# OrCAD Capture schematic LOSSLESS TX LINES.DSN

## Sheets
1 PAGE3: size A0
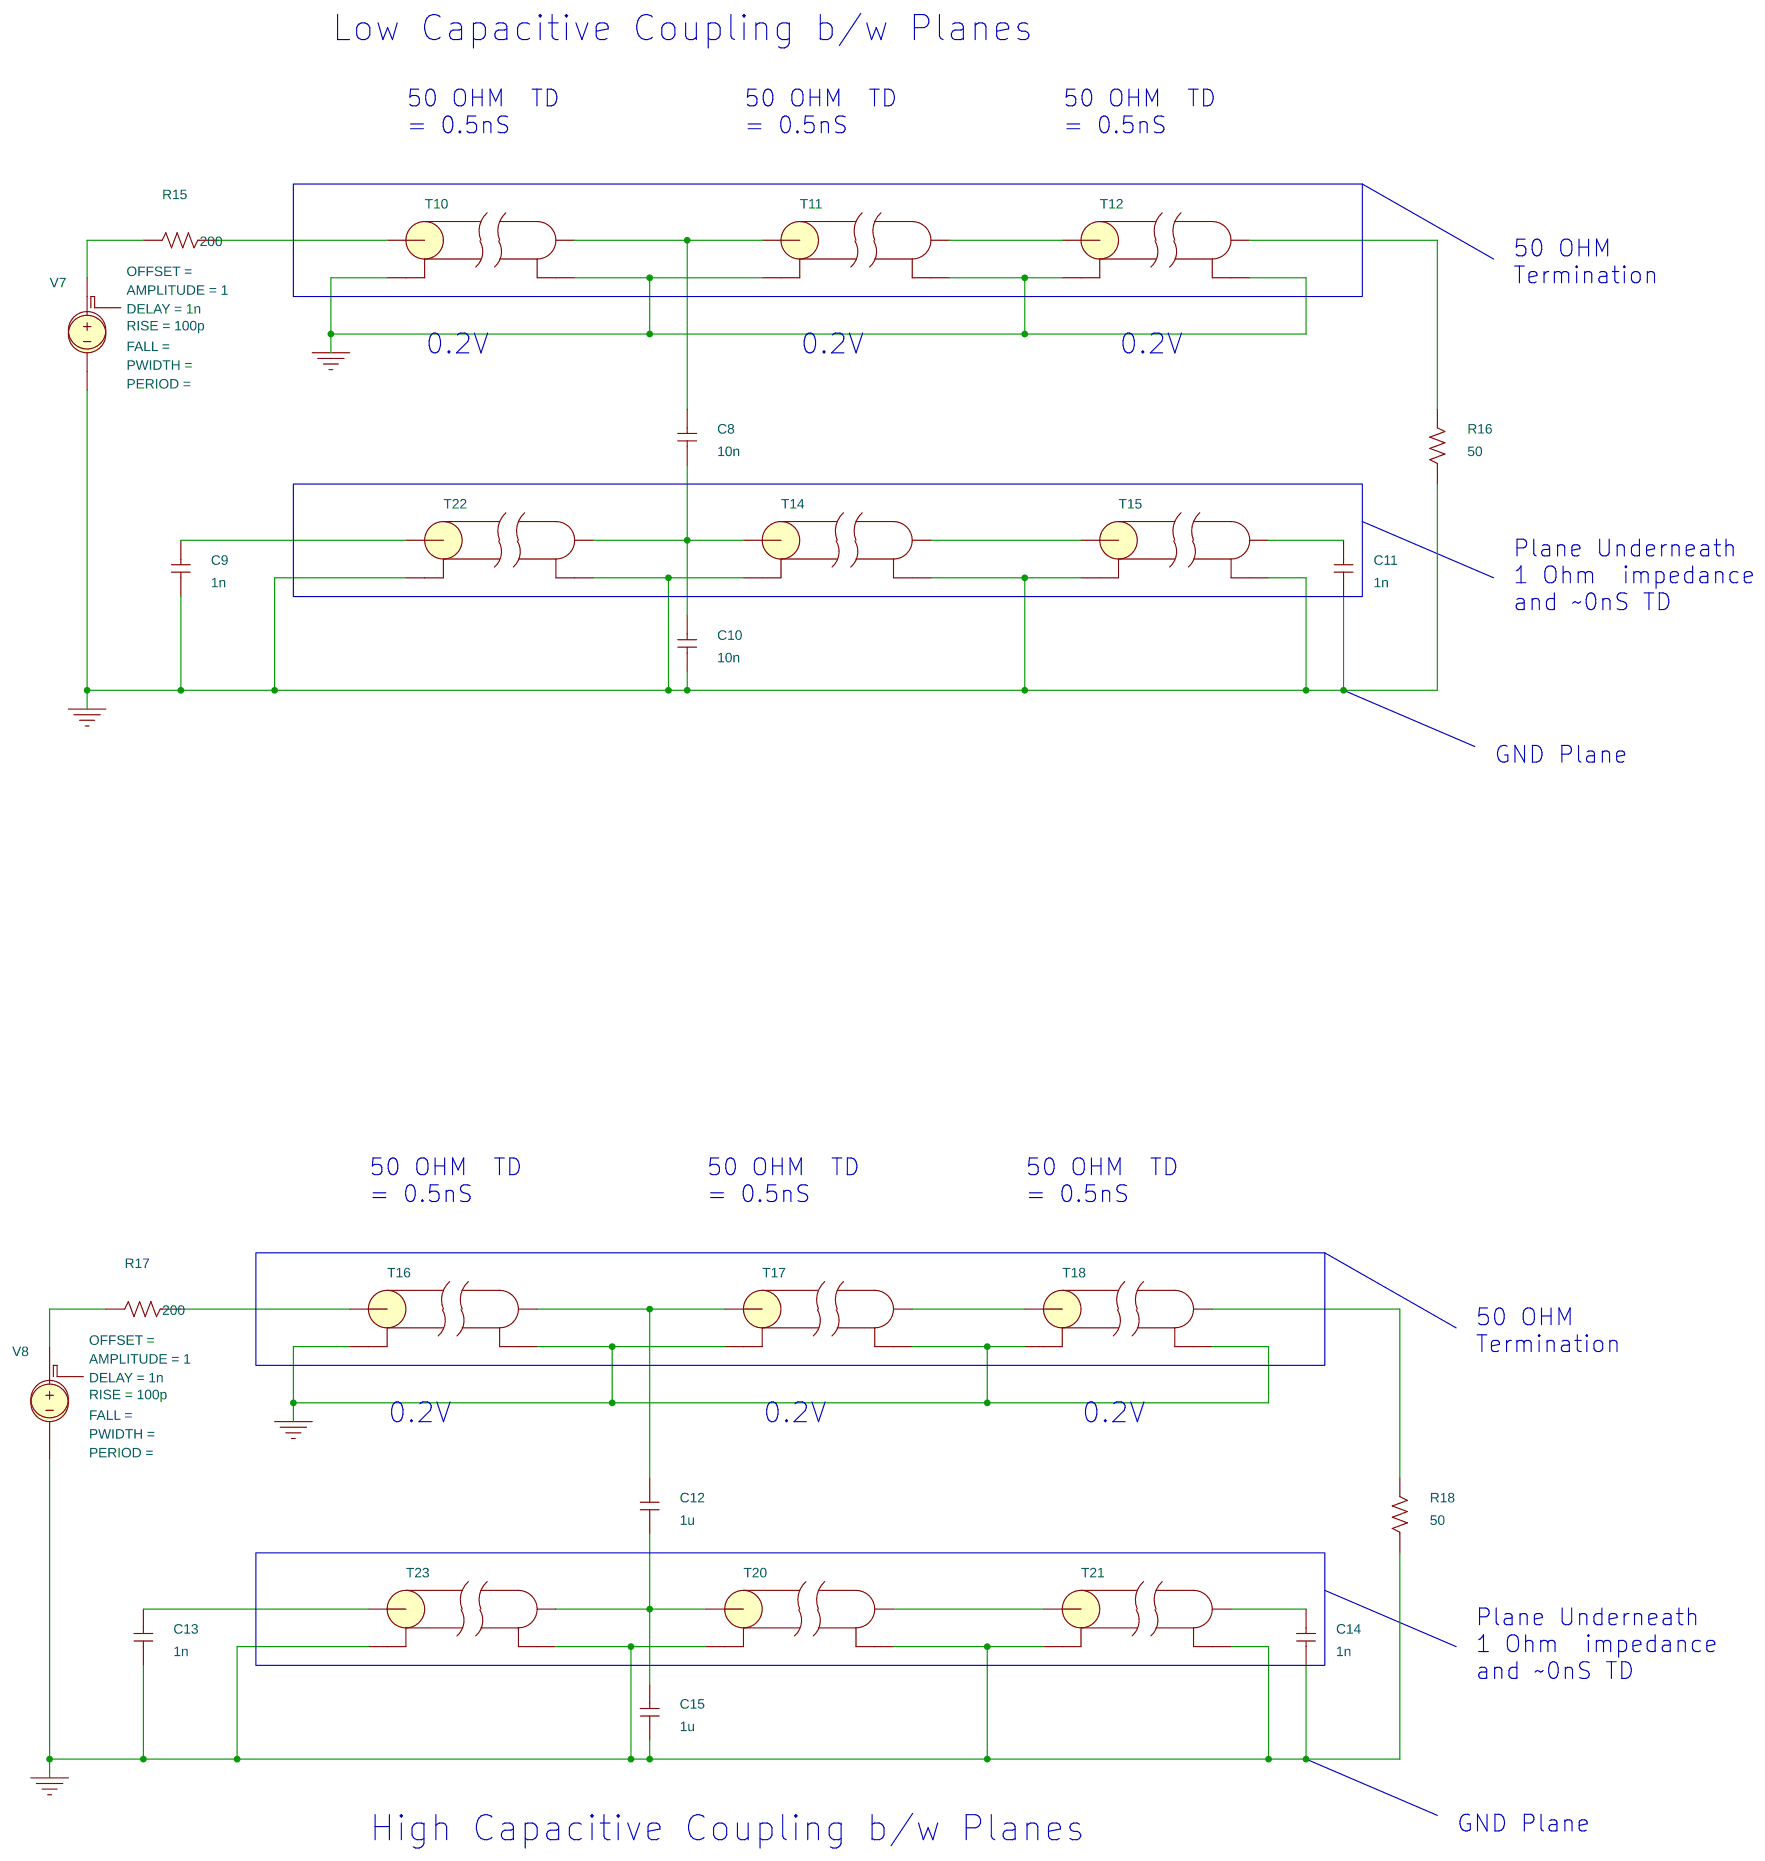
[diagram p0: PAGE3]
2 PAGE2: size A0
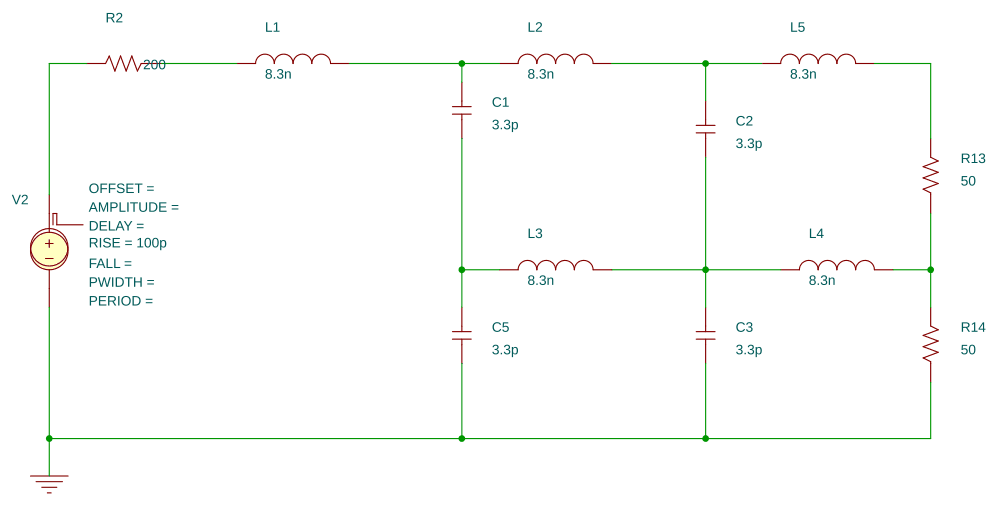
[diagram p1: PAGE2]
3 PAGE1: size A4
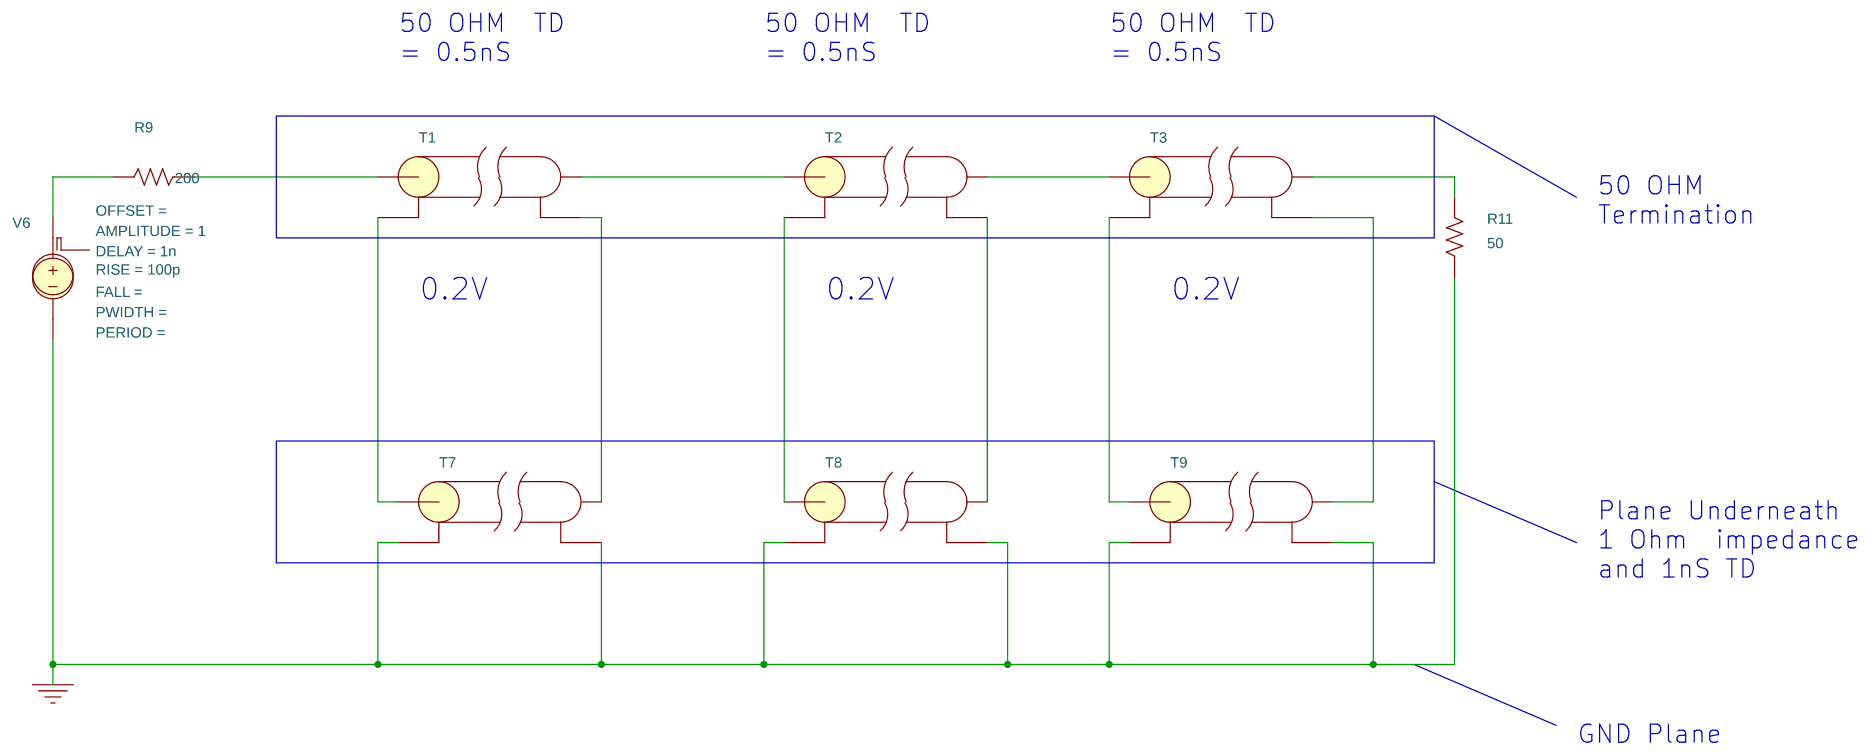
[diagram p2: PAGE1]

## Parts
sheet PAGE1
R9  200  [RC05]
R11  50  [RC05]
T1  T
T2  T
T3  T
T7  T
T8  T
T9  T
V6  ?DC|DC @DC| ?AC|AC @AC|\n+PULSE @OFFSET @AMPLITUDE+@OFFSET ?DELAY/@DELAY/~DELAY/0/ #RISE/@RISE/ #FALL/@FALL/ #PWIDTH/@PWIDTH/ #PERIOD/@PERIOD/
sheet PAGE2
C1  3.3p  [CK05]
C2  3.3p  [CK05]
C3  3.3p  [CK05]
C5  3.3p  [CK05]
L1  8.3n  [L2012C]
L2  8.3n  [L2012C]
L3  8.3n  [L2012C]
L4  8.3n  [L2012C]
L5  8.3n  [L2012C]
R2  200  [RC05]
R13  50  [RC05]
R14  50  [RC05]
V2  ?DC|DC @DC| ?AC|AC @AC|\n+PULSE @OFFSET @AMPLITUDE+@OFFSET ?DELAY/@DELAY/~DELAY/0/ #RISE/@RISE/ #FALL/@FALL/ #PWIDTH/@PWIDTH/ #PERIOD/@PERIOD/
sheet PAGE3
C8  10n  [CK05]
C9  1n  [CK05]
C10  10n  [CK05]
C11  1n  [CK05]
C12  1u  [CK05]
C13  1n  [CK05]
C14  1n  [CK05]
C15  1u  [CK05]
R15  200  [RC05]
R16  50  [RC05]
R17  200  [RC05]
R18  50  [RC05]
T10  T
T11  T
T12  T
T14  T
T15  T
T16  T
T17  T
T18  T
T20  T
T21  T
T22  T
T23  T
V7  ?DC|DC @DC| ?AC|AC @AC|\n+PULSE @OFFSET @AMPLITUDE+@OFFSET ?DELAY/@DELAY/~DELAY/0/ #RISE/@RISE/ #FALL/@FALL/ #PWIDTH/@PWIDTH/ #PERIOD/@PERIOD/
V8  ?DC|DC @DC| ?AC|AC @AC|\n+PULSE @OFFSET @AMPLITUDE+@OFFSET ?DELAY/@DELAY/~DELAY/0/ #RISE/@RISE/ #FALL/@FALL/ #PWIDTH/@PWIDTH/ #PERIOD/@PERIOD/

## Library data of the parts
R2 R9 R11 R13-R18 = R
T1-T3 T10-T12 T16-T18 = T: TD: 0.5n; Z0: 50
T7-T9 T14 T15 T20-T23 = T: TD: 1n; Z0: 1
V6-V8 = V_PULSE: AMPLITUDE: 1; DELAY: 1n; RISE: 100p
C1-C3 C5 C8-C15 = C
L1-L5 = L
V2 = V_PULSE: RISE: 100p

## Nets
0: C3.1 C5.1 C9.1 C10.1 C11.1 C13.1 C14.1 C15.1 R11.1 R14.1 R16.1 R18.1 T7.2(A-) T7.4(B-) T8.2(A-) T8.4(B-) T9.2(A-) T9.4(B-) T10.2(A-) T10.4(B-) T11.2(A-) T11.4(B-) T12.2(A-) T12.4(B-) T14.2(A-) T14.4(B-) T15.2(A-) T15.4(B-) T16.2(A-) T16.4(B-) T17.2(A-) T17.4(B-) T18.2(A-) T18.4(B-) T20.2(A-) T20.4(B-) T21.2(A-) T21.4(B-) T22.2(A-) T22.4(B-) T23.2(A-) T23.4(B-) V2.1(NVS) V6.1(NVS) V7.1(NVS) V8.1(NVS)
N17505: R9.2 V6.2(PVS)
N17515: R9.1 T1.1(A+)
N17606: T1.2(A-) T7.1(A+)
N18075: T1.3(B+) T2.1(A+)
N18113: T1.4(B-) T7.3(B+)
N18578: T3.4(B-) T9.3(B+)
N18870: R11.2 T3.3(B+)
N19026: T2.3(B+) T3.1(A+)
N19034: T3.2(A-) T9.1(A+)
N21376: T2.4(B-) T8.3(B+)
N21395: T2.2(A-) T8.1(A+)
N31030: R2.2 V2.2(PVS)
N31040: L1.1 R2.1
N31046: C1.2 L1.2 L2.1
N31060: C2.2 L2.2 L5.1
N31076: L5.2 R13.2
N31178: C1.1 C5.2 L3.1
N31182: C2.1 C3.2 L3.2 L4.1
N31638: L4.2 R13.1 R14.2
N33606: R15.2 V7.2(PVS)
N33616: R15.1 T10.1(A+)
N33622: C8.2 T10.3(B+) T11.1(A+)
N33628: T11.3(B+) T12.1(A+)
N33634: R16.2 T12.3(B+)
N33848: C9.2 T22.1(A+)
N33852: T14.3(B+) T15.1(A+)
N33856: C11.2 T15.3(B+)
N34651: C8.1 C10.2 T14.1(A+) T22.3(B+)
N37051: R17.2 V8.2(PVS)
N37061: R17.1 T16.1(A+)
N37067: C12.2 T16.3(B+) T17.1(A+)
N37083: T17.3(B+) T18.1(A+)
N37089: R18.2 T18.3(B+)
N37251: C12.1 C15.2 T20.1(A+) T23.3(B+)
N37345: C13.2 T23.1(A+)
N37365: T20.3(B+) T21.1(A+)
N37371: C14.2 T21.3(B+)

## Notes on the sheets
sheet 1
- Low Capacitive Coupling b/w Planes
- 50 OHM  TD
  = 0.5nS
- 50 OHM  TD
  = 0.5nS
- 50 OHM  TD
  = 0.5nS
- 50 OHM
  Termination
- 0.2V
- 0.2V
- 0.2V
- Plane Underneath
  1 Ohm  impedance
  and ~0nS TD
- GND Plane
- 50 OHM  TD
  = 0.5nS
- 50 OHM  TD
  = 0.5nS
- 50 OHM  TD
  = 0.5nS
- 50 OHM
  Termination
- 0.2V
- 0.2V
- 0.2V
- Plane Underneath
  1 Ohm  impedance
  and ~0nS TD
- High Capacitive Coupling b/w Planes
- GND Plane
sheet 3
- 50 OHM  TD
  = 0.5nS
- 50 OHM  TD
  = 0.5nS
- 50 OHM  TD
  = 0.5nS
- 50 OHM
  Termination
- 0.2V
- 0.2V
- 0.2V
- Plane Underneath
  1 Ohm  impedance
  and 1nS TD
- GND Plane
